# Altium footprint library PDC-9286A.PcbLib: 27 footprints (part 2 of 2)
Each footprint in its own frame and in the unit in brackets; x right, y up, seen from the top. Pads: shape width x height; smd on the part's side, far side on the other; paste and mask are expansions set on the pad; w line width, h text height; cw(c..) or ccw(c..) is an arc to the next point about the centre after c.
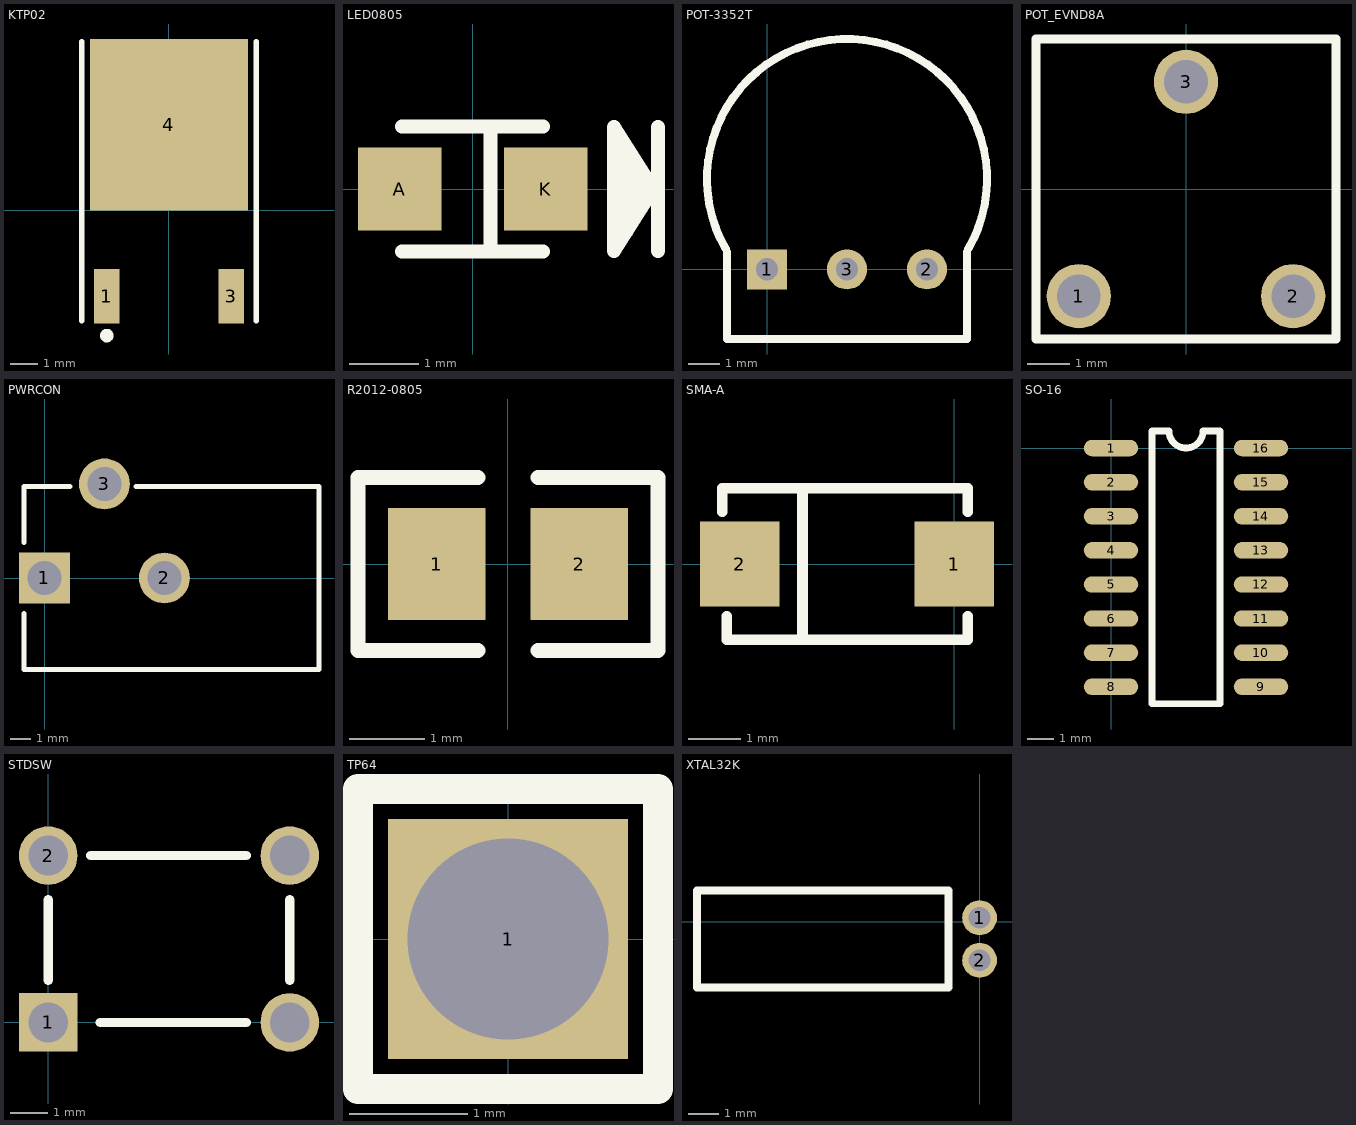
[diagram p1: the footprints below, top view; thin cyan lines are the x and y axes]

## KTP02 [mm] "PowerFLEX (D-PAK/TO-252-AA); 3 Leads (1 Cropped); Body 9.7 (inc. leads) x 6.2 mm (LxW max)"
height 2.03
pads (3):
  rect 0.95x2 smd: 1(-2.285,-3.15) 3(2.285,-3.15)
  rect 5.8x6.3 smd: 4(0,3.15)
Top Overlay:
  circle w0.25: c-2.285,-4.6 r0.125
  lines w0.2: -3.2,-4.05 -3.2,6.2 ; 3.2,-4.05 3.2,6.2

## LED0805 [mm]
pads (2):
  rect 1.2x1.2 smd: A(-1.05,0) K(1.05,0)
Top Overlay:
  lines w0.2: -1.016,-0.9 1.016,-0.9 ; -1.016,0.9 1.016,0.9
  lines w0.203: 0.254,-0.9 0.254,0.9 ; 2.087,-0.251 2.032,-0.889 ; 2.087,0.381 2.032,0.889 ; 2.214,-0.609 2.214,0.381 2.595,0 ; 2.474,-0.191 2.474,0.121 2.357,0.238 2.357,0.063 2.29,-0.004 2.29,-0.258 2.032,0 ; 2.667,-0.889 2.667,0.889 ; 2.032,-0.889 2.032,0.889 ; 2.032,-0.889 2.595,0 ; 2.032,0 2.032,0.889 ; 2.032,0 2.595,0 ; 2.032,0 2.595,0 ; 2.032,0.889 2.595,0

## POT-3352T [mil]
pads (3):
  rect 50x50 hole 28: 1(0,0)
  round 50 hole 28: 2(200,0) 3(100,0)
Top Overlay:
  lines w10: -51.55,25.5 cw(c100,113) 251.55,25.5 ; -50,22 -50,-87 250,-87 250,22

## POT_EVND8A [mm]
pads (3):
  round 1.5 hole 1.016: 1(-2.5,-2.5) 2(2.5,-2.5) 3(0,2.5)
Top Overlay:
  lines w0.2: -3.5,-3.5 -3.5,3.5 3.5,3.5 3.5,-3.5 -3.5,-3.5

## PWRCON [mil]
pads (3):
  rect 100x100 hole 67: 1(-0.33,0.33)
  round 100 hole 67: 2(235.67,0.33) 3(117.67,185.33)
Top Overlay:
  lines w10: -40.33,-69.67 -40.33,-179.67 539.67,-179.67 539.67,180.33 179.67,180.33 ; -40.33,70.33 -40.33,180.33 49.67,180.33

## R2012-0805 [mm] "Thermistor; 2 Leads"
pads (2):
  rect 1.3x1.5 smd: 1(-0.95,0) 2(0.95,0)
Top Overlay:
  lines w0.2: -0.4,-1.15 -2,-1.15 -2,1.15 -0.4,1.15 ; 0.4,-1.15 2,-1.15 2,1.15 0.4,1.15

## SMA-A [mm]
pads (2):
  rect 1.52x1.63 smd: 1(0,0) 2(-4.1,0)
Top Overlay:
  lines w0.203: -4.436,1 -4.436,1.45 0.245,1.45 ; -4.346,-1 -4.346,-1.45 0.254,-1.45 0.254,-1 ; -2.9,-1.45 -2.9,1.45 ; 0.254,1 0.254,1.45

## SO-16 [mil]
pads (16):
  oval 80x24 smd: 1(0,0) 2(0,-50) 3(0,-100) 4(0,-150) 5(0,-200) 6(0,-250) 7(0,-300) 8(0,-350) 9(220,-350) 10(220,-300) 11(220,-250) 12(220,-200) 13(220,-150) 14(220,-100) 15(220,-50) 16(220,0)
Top Overlay:
  lines w10: 60,-375 160,-375 160,25 135,25 cw(c110,25) 85,25 60,25 60,-375

## STDSW [mil]
pads (4):
  rect 62x62 hole 42: 1(0,0)
  round 62 hole 42: 2(0,177) ""(256,0) ""(256,177)
Top Overlay:
  lines w10: 0,45 0,130 ; 45,177 210,177 ; 55,0 210,0 ; 256,45 256,130

## TP64 [mil]
pads (1):
  rect 80x80 hole 67: 1(0,0)
Top Overlay:
  lines w10: -50,-50 50,-50 50,50 -50,50 -50,-50

## XTAL32K [mil]
pads (2):
  round 45 hole 28: 1(0,5) 2(0,-50)
Top Overlay:
  lines w10: -365,-85 -365,40 -40,40 -40,-85 -365,-85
